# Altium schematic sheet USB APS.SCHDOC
size A; PageSetup: Record=PageOptions¦CenterHorizontal=True¦CenterVertical=True¦PrintScale=1.11¦XCorrection=1.00¦YCorrection=1.00¦PrintKind=0¦BorderSize=5000000¦LeftOffset=0¦BottomOffset=0¦Orientation=2¦PaperLength=1000¦PaperWidth=1000¦Scale=100¦PaperSource=7¦PrintQuality=-3¦MediaType=1¦DitherType=10¦PrintScaleMode=1¦PaperKind=Letter¦PaperIndex=1
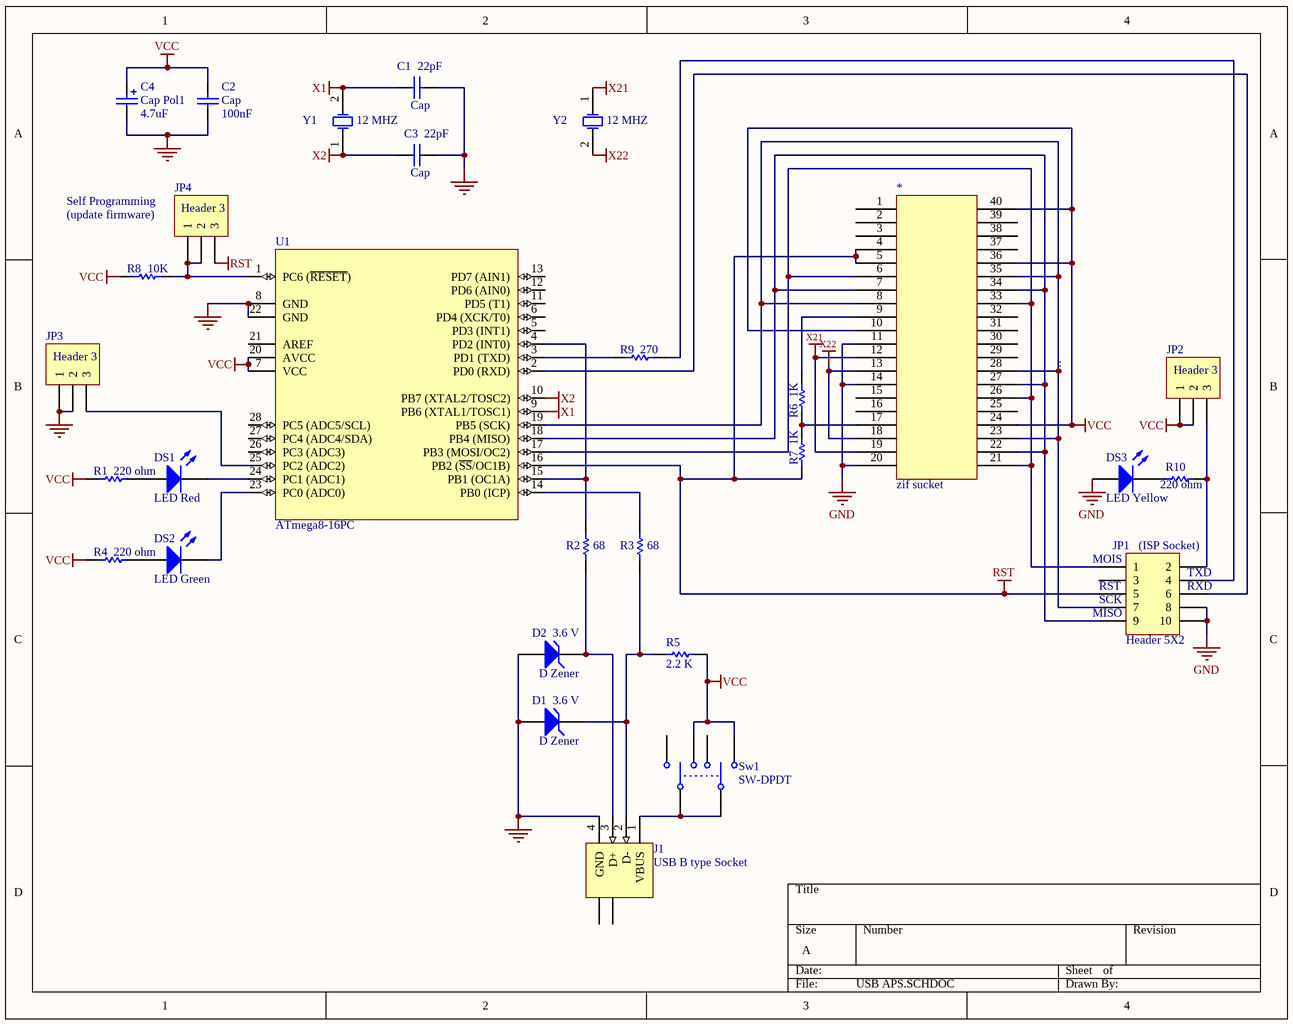
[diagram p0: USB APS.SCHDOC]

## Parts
*  zif sucket  [40P6]
C1  Cap  value 22pF  [RAD-0.1]
C2  Cap  value 100nF  [RAD-0.2]
C3  Cap  value 22pF  [RAD-0.1]
C4  Cap Pol1  value 4.7uF  [CAPPR3.5-8x5]
D1  D Zener  value 3.6 V  [DIODE-0.4]
D2  D Zener  value 3.6 V  [DIODE-0.4]
DS1  LED Red  [LED3mm]
DS2  LED Green  [LED3mm]
DS3  LED Yellow  [LED3mm]
J1  USB B type Socket  [1-1470156]
JP1_(ISP_Socket)  Header 5X2  [HDR2X5]
JP2  Header 3  [HDR1X3]
JP3  Header 3  [HDR1X3]
JP4  Header 3  [HDR1X3]
R1  value 220 ohm  [AXIAL-0.4]  (hidden comment: Res1)
R2  value 68  [AXIAL-0.4]  (hidden comment: Res1)
R3  value 68  [AXIAL-0.4]  (hidden comment: Res1)
R4  value 220 ohm  [AXIAL-0.4]  (hidden comment: Res1)
R5  value 2.2 K  [AXIAL-0.4]  (hidden comment: Res1)
R6  value 1K  [AXIAL-0.4]  (hidden comment: Res1)
R7  value 1K  [AXIAL-0.4]  (hidden comment: Res1)
R8  value 10K  [AXIAL-0.4]  (hidden comment: Res1)
R9  value 270  [AXIAL-0.4]  (hidden comment: Res1)
R10  value 220 ohm  [AXIAL-0.4]  (hidden comment: Res1)
Sw1  SW-DPDT  [DPDT-6]
U1  ATmega8-16PC  [28P3]
Y1  Y1  value 12 MHZ  [xtal - duplicate]
Y2  Y2  value 12 MHZ  [xtal - duplicate]

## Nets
GND: *.11 *.14 *.20 C1.2 C2.1 C3.2 C4.2 D1.1(A) D2.1(A) DS3.1(A) J1.4(GND) JP1_(ISP_Socket).8 JP1_(ISP_Socket).10 JP3.1 JP3.2 U1.8(GND) U1.22(GND)
RST: *.4 *.5 JP1_(ISP_Socket).5 JP4.3 R7.1 U1.16(PB2_(~{SS}/OC1B))
VCC: *.10 *.24 *.36 *.40 C2.2 C4.1 JP2.1 JP2.2 R1.1 R4.1 R5.2 R8.1 Sw1.3 Sw1.6 U1.7(VCC) U1.20(AVCC)
X1: C1.1 U1.9(PB6_(XTAL1/TOSC1)) Y1.2(OSC2)
X2: C3.1 U1.10(PB7_(XTAL2/TOSC2)) Y1.1(OSC1)
X21: *.12 *.19 Y2.1(OSC1)
X22: *.13 *.18 Y2.2(OSC2)
Net*_6: *.6 *.21 *.26 *.33 JP1_(ISP_Socket).1 U1.17(PB3_(MOSI/OC2))
Net*_7: *.7 *.22 *.27 *.34 JP1_(ISP_Socket).9 U1.18(PB4_(MISO))
Net*_8: *.8 *.23 *.28 *.35 JP1_(ISP_Socket).7 U1.19(PB5_(SCK))
Net*_9: *.9 R6.1
Net*_17: *.17 R6.2 R7.2
NetD1_2: D1.2(K) J1.2(D-) R3.1 R5.1
NetD2_2: D2.2(K) J1.3(D+) R2.1
NetDS1_1: DS1.1(A) R1.2
NetDS1_2: DS1.2(K) U1.24(PC1_(ADC1))
NetDS2_1: DS2.1(A) R4.2
NetDS2_2: DS2.2(K) U1.23(PC0_(ADC0))
NetJ1_1: J1.1(VBUS) Sw1.1 Sw1.4
NetJP1_(ISP_Socket)_2: JP1_(ISP_Socket).2 JP2.3 R10.2
NetJP1_(ISP_Socket)_4: JP1_(ISP_Socket).4 R9.2
NetJP1_(ISP_Socket)_6: JP1_(ISP_Socket).6 U1.2(PD0_(RXD))
NetJP3_3: JP3.3 U1.25(PC2_(ADC2))
NetJP4_1: JP4.1 JP4.2 R8.2 U1.1(PC6_(~{RESET}))
NetR2_2: R2.2 U1.4(PD2_(INT0)) U1.15(PB1_(OC1A))
NetR3_2: R3.2 U1.14(PB0_(ICP))
NetR9_1: R9.1 U1.3(PD1_(TXD))

Not connected (* = marked no-connect by the designer): * 1 2 3 15 16 25 29 30 31 32 37 38 39; DS3 2(K); J1 5(SHLD) 6(SHLD); JP1_(ISP_Socket) 3; R10 1; Sw1 2 5; U1 5(PD3_(INT1)) 6(PD4_(XCK/T0)) 11(PD5_(T1)) 12(PD6_(AIN0)) 13(PD7_(AIN1)) 21(AREF) 26(PC3_(ADC3)) 27(PC4_(ADC4/SDA)) 28(PC5_(ADC5/SCL))

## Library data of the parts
* = Component_1
C1-C3 = Cap: Capacitor
C4 = Cap Pol1: Polarized Capacitor (Radial)
D1 D2 = D Zener: Zener Diode
DS1-DS3 = LED0: Typical INFRARED GaAs LED
J1 = 1-1470156-1: USB 1.1, Right Angle, Thru-Hole, B Type, Receptacle, 4 Position, White; ContactMaterial: Phosphor Bronze; ContactPlating: Gold over Nickel; TerminationLength: 3.00mm [0.118in.]; PCB_Layout: Complies with manufacturer's recommendation.; DrillSize: Corresponds to nominal value.; PanelGround: Without
JP1_(ISP_Socket) = Header 5X2: Header, 5-Pin, Dual row
JP2-JP4 = Header 3: Header, 3-Pin
R1-R10 = Res1: Resistor
Sw1 = SW-DPDT: Double-Pole, Double-Throw Switch
U1 = ATmega8-16PC: 8-Bit AVR Microcontroller with 8K Bytes of In-System Programmable Flash Memory; Package Information: Latest Revision: revB, Sep-2001
Y1 Y2 = XTAL: Crystal Oscillator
